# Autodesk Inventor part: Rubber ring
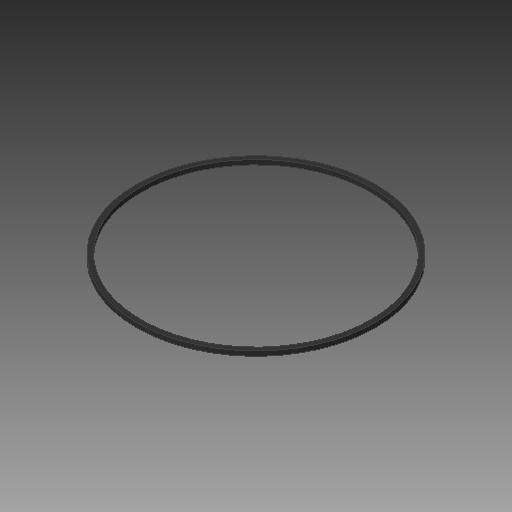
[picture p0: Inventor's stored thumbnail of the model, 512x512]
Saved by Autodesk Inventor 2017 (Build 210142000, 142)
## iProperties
Created: 2020-03
Part Number: Rubber ring
Material: Rubber, Silicone
Document SubType Name: Modeling
Designer: user
Density: 1.25 g/cm^3
Appearance: Rubber - Black
Mass: 12.692 g
Surface Area: 101.536 cm^2
Volume: 10.1536 cm^3
Author: user
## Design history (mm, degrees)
sketch "Sketch1"
  geometry: C1 r 99 at (0, 0); C2 r 103 at (0, 0); 1 further point
  constraints: 2 centre point, 1 coincident
  dimensions: "d0" = 198 diameter of C1; "d1" = 4 radial gap between concentric circles of C1 C2
extrude "Extrusion1" new body sketch "Sketch1" distance "d2" = 4; taper "d3" = 0 deg
body "Solid1"
